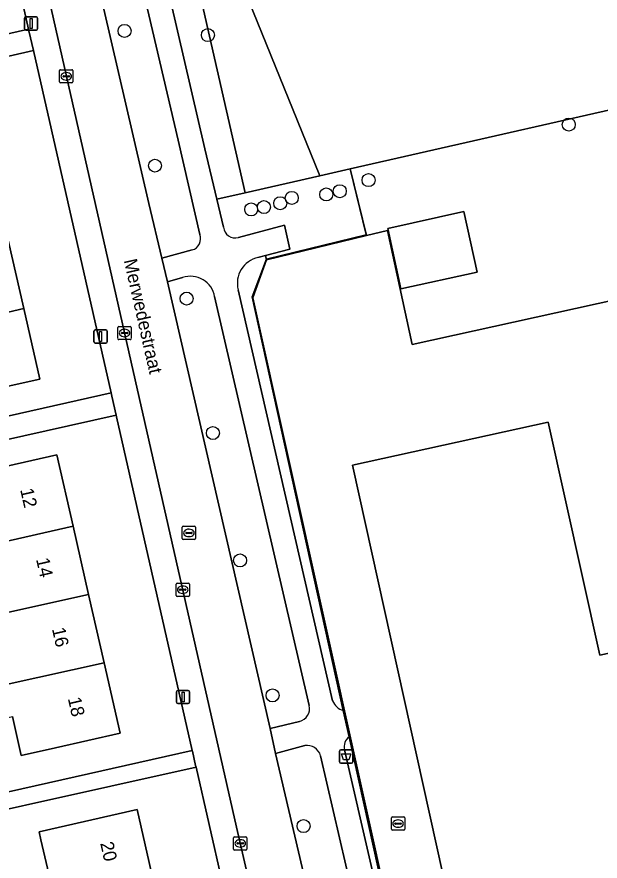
# Model space of a CAD drawing. Extents: x 157320 to 158835, y 386650 to 388491.
# Drawn here: x 157767.5 to 157811.4, y 387636.3 to 387699.9 of the extents above; entities that cross this region are included whole.
import ezdxf

# ---------------------------------------------------------------- set-up
doc = ezdxf.new("R2010")
doc.units = 0
for name, color, linetype in [('IMGEO_Afvalbak', 7, 'Continuous'), ('IMGEO_Boom', 7, 'Continuous'), ('IMGEO_Erf', 7, 'Continuous'), ('IMGEO_Groenvoorziening', 7, 'Continuous'), ('IMGEO_Hek', 7, 'Continuous'), ('IMGEO_Kolk', 7, 'Continuous'), ('IMGEO_Lichtmast', 7, 'Continuous'), ('IMGEO_Openbare_ruimte_label', 7, 'Continuous'), ('IMGEO_Pand', 7, 'Continuous'), ('IMGEO_Pand_nummerreeks', 7, 'Continuous'), ('IMGEO_Parkeervlak_open', 7, 'Continuous'), ('IMGEO_Rijbaan_lokaal_open', 7, 'Continuous'), ('IMGEO_Rioolput', 7, 'Continuous'), ('IMGEO_Voetpad_halfverhard', 7, 'Continuous'), ('IMGEO_Voetpad_open', 7, 'Continuous')]:
    doc.layers.add(name, color=color, linetype=linetype)

msp = doc.modelspace()

# ---------------------------------------------------------------- linework, layer by layer
at = {"layer": 'IMGEO_Afvalbak'}
for p, q in [((157791.814, 387643.776), (157791.814, 387644.576)), ((157791.814, 387644.576), (157791.814, 387643.776)), ((157791.914, 387644.676), (157792.704, 387644.676)), ((157792.704, 387644.676), (157791.914, 387644.676)), ((157792.804, 387644.576), (157792.804, 387643.776)), ((157792.804, 387643.776), (157792.804, 387644.576)), ((157792.704, 387643.676), (157791.914, 387643.676)), ((157791.914, 387643.676), (157792.704, 387643.676))]:
    msp.add_line(p, q, dxfattribs=at)
msp.add_lwpolyline([(157791.957, 387644.39), (157792.661, 387644.39), (157792.512, 387643.92), (157792.106, 387643.92), (157791.957, 387644.39)], dxfattribs=at)
for centre, start, end in [((157791.914, 387644.576), 90, 180), ((157791.914, 387644.576), 90, 180), ((157792.704, 387644.576), 0, 90), ((157792.704, 387644.576), 360, 90), ((157791.914, 387643.776), 180, 270), ((157791.914, 387643.776), 180, 270), ((157792.704, 387643.776), 270, 0), ((157792.704, 387643.776), 270, 0)]:
    msp.add_arc(centre, 0.1, start, end, dxfattribs=at)
at = {"layer": 'IMGEO_Boom'}
for centre in [(157775.609, 387698.881), (157781.893, 387698.565), (157809.078, 387691.821), (157777.905, 387688.72), (157793.996, 387687.63), (157790.81, 387686.549), (157791.828, 387686.798), (157787.337, 387685.891), (157788.21, 387686.292), (157785.151, 387685.42), (157786.115, 387685.598), (157780.29, 387678.698), (157782.268, 387668.563), (157784.312, 387658.961), (157786.76, 387648.787), (157789.095, 387638.93)]:
    msp.add_circle(centre, 0.489, dxfattribs=at)
at = {"layer": 'IMGEO_Erf'}
for points in [[(157744.821, 387693.675), (157768.381, 387699.017), (157764.859, 387714.548)], [(157784.941, 387701.215), (157790.321, 387687.956), (157792.617, 387688.478), (157819.163, 387694.512)], [(157748.731, 387665.763), (157774.601, 387671.588), (157768.748, 387697.397), (157745.976, 387692.171)], [(157766.849, 387683.112), (157768.019, 387677.941), (157769.219, 387672.637), (157764.343, 387671.533)], [(157756.011, 387639.067), (157780.714, 387644.628), (157775.009, 387669.789), (157774.984, 387669.899), (157748.592, 387664.011)], [(157763.513, 387665.337), (157770.505, 387666.932), (157771.734, 387661.545), (157772.908, 387656.394), (157774.083, 387651.242), (157775.292, 387645.942), (157770.418, 387644.831), (157767.833, 387644.241), (157767.158, 387647.199)], [(157786.883, 387617.427), (157781, 387643.367), (157755.052, 387637.604), (157750.85, 387636.671), (157750.482, 387636.589), (157751.038, 387633.845)], [(157769.895, 387635.327), (157769.305, 387637.903), (157769.173, 387638.5), (157776.551, 387640.189), (157777.77, 387634.865)]]:
    msp.add_lwpolyline(points, dxfattribs=at)
at = {"layer": 'IMGEO_Groenvoorziening'}
for points in [[(157781.285, 387683.528), (157779.645, 387690.655), (157777.159, 387701.293), (157772.834, 387719.515), (157770.315, 387730.462), (157767.54, 387729.135), (157767.721, 387727.843), (157768.836, 387723.063), (157770.575, 387715.53), (157777.429, 387685.881), (157778.41, 387681.752), (157780.707, 387682.368)], [(157819.163, 387694.512), (157792.617, 387688.478), (157793.85, 387683.459), (157795.419, 387683.841), (157797.286, 387675.235), (157829.765, 387682.405)], [(157792.617, 387688.478), (157790.321, 387687.956), (157784.703, 387686.679), (157782.572, 387686.195), (157783.074, 387684.079)], [(157784.185, 387683.301), (157787.667, 387684.235), (157788.066, 387682.433), (157786.231, 387681.945), (157786.315, 387681.625), (157793.85, 387683.459), (157792.617, 387688.478)], [(157786.315, 387681.625), (157786.231, 387681.945), (157785.66, 387681.793)], [(157792.188, 387644.685), (157802.528, 387599.779), (157802.788, 387599.832), (157801.253, 387606.747), (157785.269, 387678.768), (157786.315, 387681.625)], [(157779.986, 387680.279), (157778.84, 387679.961), (157786.577, 387646.289), (157788.786, 387646.819)], [(157784.175, 387679.368), (157791.291, 387648.372)], [(157789.521, 387648.019), (157782.399, 387678.849)], [(157792.087, 387647.658), (157792.525, 387645.671)], [(157789.187, 387645.002), (157786.982, 387644.405), (157789.443, 387633.877), (157797.77, 387598.149), (157800.871, 387598.887), (157790.384, 387644.236)]]:
    msp.add_lwpolyline(points, dxfattribs=at)
msp.add_lwpolyline([(157801.175, 387685.256), (157802.17, 387680.689), (157796.438, 387679.428), (157795.445, 387683.997)], close=True, dxfattribs=at)
for centre, radius, start, end in [((157783.962, 387684.164), 0.892, 185.49428, 284.50091), ((157780.464, 387683.213), 0.879, 286.05214, 20.97592), ((157786.076, 387679.871), 1.966, 102.21251, 194.82329), ((157780.588, 387678.544), 1.837, 9.5637, 109.13236), ((157792.362, 387648.766), 1.141, 200.17079, 256.04596), ((157788.553, 387647.787), 0.995, 283.53209, 13.49297), ((157793.147, 387644.908), 0.985, 129.18724, 193.07344), ((157789.358, 387643.951), 1.065, 15.51084, 99.25611)]:
    msp.add_arc(centre, radius, start, end, dxfattribs=at)
at = {"layer": 'IMGEO_Hek'}
for points in [[(157784.941, 387701.215), (157790.321, 387687.956)], [(157793.824, 387683.52), (157792.617, 387688.478)], [(157792.087, 387647.658), (157785.216, 387678.831), (157786.296, 387681.687), (157793.824, 387683.52)], [(157802.675, 387599.617), (157792.525, 387645.671)]]:
    msp.add_lwpolyline(points, dxfattribs=at)
at = {"layer": 'IMGEO_Kolk'}
for p, q in [((157770.721, 387695.032), (157770.721, 387695.884)), ((157770.796, 387695.958), (157771.648, 387695.958)), ((157771.722, 387695.884), (157771.722, 387695.032)), ((157770.98, 387695.452), (157770.98, 387695.464)), ((157771.418, 387695.415), (157771.02, 387695.415)), ((157771.023, 387695.501), (157771.421, 387695.501)), ((157771.209, 387695.738), (157771.234, 387695.738)), ((157771.464, 387695.464), (157771.464, 387695.452)), ((157771.648, 387694.958), (157770.796, 387694.958)), ((157771.232, 387695.178), (157771.207, 387695.178)), ((157775.112, 387675.679), (157775.112, 387676.531)), ((157775.187, 387676.605), (157776.039, 387676.605)), ((157775.6, 387676.385), (157775.625, 387676.385)), ((157776.113, 387676.531), (157776.113, 387675.679)), ((157776.039, 387675.605), (157775.187, 387675.605)), ((157775.371, 387676.099), (157775.371, 387676.111)), ((157775.809, 387676.062), (157775.411, 387676.062)), ((157775.414, 387676.148), (157775.812, 387676.148)), ((157775.623, 387675.825), (157775.598, 387675.825)), ((157775.855, 387676.111), (157775.855, 387676.099)), ((157779.496, 387656.325), (157779.496, 387657.177)), ((157779.571, 387657.251), (157780.423, 387657.251)), ((157780.497, 387657.177), (157780.497, 387656.325)), ((157779.755, 387656.745), (157779.755, 387656.757)), ((157780.193, 387656.708), (157779.795, 387656.708)), ((157779.798, 387656.794), (157780.196, 387656.794)), ((157780.007, 387656.471), (157779.982, 387656.471)), ((157779.984, 387657.031), (157780.009, 387657.031)), ((157780.239, 387656.757), (157780.239, 387656.745)), ((157780.423, 387656.251), (157779.571, 387656.251)), ((157783.832, 387637.2), (157783.832, 387638.052)), ((157783.907, 387638.126), (157784.759, 387638.126)), ((157784.833, 387638.052), (157784.833, 387637.2)), ((157784.091, 387637.62), (157784.091, 387637.632)), ((157784.529, 387637.583), (157784.131, 387637.583)), ((157784.134, 387637.669), (157784.532, 387637.669)), ((157784.343, 387637.346), (157784.318, 387637.346)), ((157784.32, 387637.906), (157784.345, 387637.906)), ((157784.575, 387637.632), (157784.575, 387637.62)), ((157784.759, 387637.126), (157783.907, 387637.126))]:
    msp.add_line(p, q, dxfattribs=at)
for points in [[(157770.721, 387695.032), (157770.721, 387695.884)], [(157770.796, 387695.958), (157771.648, 387695.958)], [(157771.722, 387695.884), (157771.722, 387695.032)], [(157771.648, 387694.958), (157770.796, 387694.958)], [(157775.112, 387675.679), (157775.112, 387676.531)], [(157775.187, 387676.605), (157776.039, 387676.605)], [(157776.113, 387676.531), (157776.113, 387675.679)], [(157776.039, 387675.605), (157775.187, 387675.605)], [(157779.496, 387656.325), (157779.496, 387657.177)], [(157779.571, 387657.251), (157780.423, 387657.251)], [(157780.497, 387657.177), (157780.497, 387656.325)], [(157780.423, 387656.251), (157779.571, 387656.251)], [(157783.832, 387637.2), (157783.832, 387638.052)], [(157783.907, 387638.126), (157784.759, 387638.126)], [(157784.833, 387638.052), (157784.833, 387637.2)], [(157784.759, 387637.126), (157783.907, 387637.126)]]:
    msp.add_lwpolyline(points, dxfattribs=at)
for centre, radius, start, end in [((157770.798, 387695.882), 0.0765, 91.55205, 178.44795), ((157770.798, 387695.882), 0.0765, 91.55205, 178.44795), ((157771.646, 387695.882), 0.0765, 1.55205, 88.44795), ((157771.646, 387695.882), 0.0765, 1.55205, 88.44795), ((157771.02, 387695.461), 0.0403, 85.87752, 175.75265), ((157771.017, 387695.451), 0.0366, 178.93798, 274.71019), ((157771.421, 387695.458), 0.043, 264.86636, 352.45326), ((157771.425, 387695.463), 0.0386, 1.73085, 96.63898), ((157770.798, 387695.034), 0.0765, 181.55205, 268.44795), ((157770.798, 387695.034), 0.0765, 181.55205, 268.44795), ((157771.646, 387695.034), 0.0765, 271.55205, 358.44795), ((157771.646, 387695.034), 0.0765, 271.55205, 358.44795), ((157775.189, 387676.529), 0.0765, 91.55205, 178.44795), ((157775.189, 387676.529), 0.0765, 91.55205, 178.44795), ((157776.037, 387676.529), 0.0765, 1.55205, 88.44795), ((157776.037, 387676.529), 0.0765, 1.55205, 88.44795), ((157775.189, 387675.681), 0.0765, 181.55205, 268.44795), ((157775.189, 387675.681), 0.0765, 181.55205, 268.44795), ((157775.411, 387676.108), 0.0403, 85.87752, 175.75265), ((157775.408, 387676.098), 0.0366, 178.93798, 274.71019), ((157775.812, 387676.105), 0.043, 264.86636, 352.45326), ((157775.816, 387676.11), 0.0386, 1.73085, 96.63898), ((157776.037, 387675.681), 0.0765, 271.55205, 358.44795), ((157776.037, 387675.681), 0.0765, 271.55205, 358.44795), ((157779.573, 387657.175), 0.0765, 91.55205, 178.44795), ((157779.573, 387657.175), 0.0765, 91.55205, 178.44795), ((157780.421, 387657.175), 0.0765, 1.55205, 88.44795), ((157780.421, 387657.175), 0.0765, 1.55205, 88.44795), ((157779.795, 387656.754), 0.0403, 85.87752, 175.75265), ((157779.792, 387656.744), 0.0366, 178.93798, 274.71019), ((157780.196, 387656.751), 0.043, 264.86636, 352.45326), ((157780.2, 387656.756), 0.0386, 1.73085, 96.63898), ((157779.573, 387656.327), 0.0765, 181.55205, 268.44795), ((157779.573, 387656.327), 0.0765, 181.55205, 268.44795), ((157780.421, 387656.327), 0.0765, 271.55205, 358.44795), ((157780.421, 387656.327), 0.0765, 271.55205, 358.44795), ((157783.909, 387638.05), 0.0765, 91.55205, 178.44795), ((157783.909, 387638.05), 0.0765, 91.55205, 178.44795), ((157784.757, 387638.05), 0.0765, 1.55205, 88.44795), ((157784.757, 387638.05), 0.0765, 1.55205, 88.44795), ((157784.131, 387637.629), 0.0403, 85.87752, 175.75265), ((157784.128, 387637.619), 0.0366, 178.93798, 274.71019), ((157784.532, 387637.626), 0.043, 264.86636, 352.45326), ((157784.536, 387637.631), 0.0386, 1.73085, 96.63898), ((157783.909, 387637.202), 0.0765, 181.55205, 268.44795), ((157783.909, 387637.202), 0.0765, 181.55205, 268.44795), ((157784.757, 387637.202), 0.0765, 271.55205, 358.44795), ((157784.757, 387637.202), 0.0765, 271.55205, 358.44795)]:
    msp.add_arc(centre, radius, start, end, dxfattribs=at)
for centre, major_axis, ratio, start_param, end_param in [((157771.208, 387695.458), (-0.387, 0.002), 0.722429, 4.712389, 7.853982), ((157771.233, 387695.458), (-0.39, 0.002), 0.717154, 1.570796, 4.712389), ((157775.599, 387676.105), (-0.387, 0.002), 0.722429, 4.712389, 7.853982), ((157775.624, 387676.105), (-0.39, 0.002), 0.717154, 1.570796, 4.712389), ((157779.983, 387656.751), (-0.387, 0.002), 0.722429, 4.712389, 7.853982), ((157780.008, 387656.751), (-0.39, 0.002), 0.717154, 1.570796, 4.712389), ((157784.319, 387637.626), (-0.387, 0.002), 0.722429, 4.712389, 7.853982), ((157784.344, 387637.626), (-0.39, 0.002), 0.717154, 1.570796, 4.712389)]:
    msp.add_ellipse(centre, major_axis=major_axis, ratio=ratio, start_param=start_param, end_param=end_param, dxfattribs=at)
at = {"layer": 'IMGEO_Lichtmast'}
for p, q in [((157768.076, 387699.039), (157768.076, 387699.839)), ((157768.076, 387699.839), (157768.076, 387699.039)), ((157768.176, 387699.939), (157768.966, 387699.939)), ((157768.966, 387699.939), (157768.176, 387699.939)), ((157769.066, 387699.839), (157769.066, 387699.039)), ((157769.066, 387699.039), (157769.066, 387699.839)), ((157768.966, 387698.939), (157768.176, 387698.939)), ((157768.176, 387698.939), (157768.966, 387698.939)), ((157773.308, 387675.447), (157773.308, 387676.247)), ((157773.308, 387676.247), (157773.308, 387675.447)), ((157773.408, 387676.347), (157774.198, 387676.347)), ((157774.198, 387676.347), (157773.408, 387676.347)), ((157774.298, 387676.247), (157774.298, 387675.447)), ((157774.298, 387675.447), (157774.298, 387676.247)), ((157774.198, 387675.347), (157773.408, 387675.347)), ((157773.408, 387675.347), (157774.198, 387675.347)), ((157779.521, 387648.263), (157779.521, 387649.063)), ((157779.521, 387649.063), (157779.521, 387648.263)), ((157779.621, 387649.163), (157780.411, 387649.163)), ((157780.411, 387649.163), (157779.621, 387649.163)), ((157780.511, 387649.063), (157780.511, 387648.263)), ((157780.511, 387648.263), (157780.511, 387649.063)), ((157780.411, 387648.163), (157779.621, 387648.163)), ((157779.621, 387648.163), (157780.411, 387648.163))]:
    msp.add_line(p, q, dxfattribs=at)
for points in [[(157768.496, 387699.814), (157768.646, 387699.814), (157768.646, 387699.064), (157768.496, 387699.064), (157768.496, 387699.814)], [(157773.728, 387676.222), (157773.878, 387676.222), (157773.878, 387675.472), (157773.728, 387675.472), (157773.728, 387676.222)], [(157779.941, 387649.038), (157780.091, 387649.038), (157780.091, 387648.288), (157779.941, 387648.288), (157779.941, 387649.038)]]:
    msp.add_lwpolyline(points, dxfattribs=at)
for centre, start, end in [((157768.176, 387699.839), 90, 180), ((157768.176, 387699.839), 90, 180), ((157768.966, 387699.839), 0, 90), ((157768.966, 387699.839), 360, 90), ((157768.176, 387699.039), 180, 270), ((157768.176, 387699.039), 180, 270), ((157768.966, 387699.039), 270, 0), ((157768.966, 387699.039), 270, 0), ((157773.408, 387676.247), 90, 180), ((157773.408, 387676.247), 90, 180), ((157774.198, 387676.247), 0, 90), ((157774.198, 387676.247), 360, 90), ((157773.408, 387675.447), 180, 270), ((157773.408, 387675.447), 180, 270), ((157774.198, 387675.447), 270, 0), ((157774.198, 387675.447), 270, 0), ((157779.621, 387649.063), 90, 180), ((157779.621, 387649.063), 90, 180), ((157780.411, 387649.063), 0, 90), ((157780.411, 387649.063), 360, 90), ((157779.621, 387648.263), 180, 270), ((157779.621, 387648.263), 180, 270), ((157780.411, 387648.263), 270, 0), ((157780.411, 387648.263), 270, 0)]:
    msp.add_arc(centre, 0.1, start, end, dxfattribs=at)
at = {"layer": 'IMGEO_Pand'}
for points in [[(157801.175, 387685.256), (157795.445, 387683.997), (157796.438, 387679.428), (157802.17, 387680.689)], [(157766.849, 387683.112), (157759.372, 387681.419), (157760.079, 387678.295), (157751.782, 387676.418), (157750.18, 387676.056), (157750.672, 387673.883), (157768.019, 387677.941)], [(157768.019, 387677.941), (157750.672, 387673.883), (157751.198, 387671.555), (157752.8, 387671.917), (157761.098, 387673.795), (157761.743, 387670.945), (157764.343, 387671.533), (157769.219, 387672.637)], [(157834.01, 387656.824), (157836.938, 387657.47), (157833.032, 387675.058), (157831.465, 387674.711), (157818.262, 387671.784), (157822.16, 387654.192), (157811.41, 387651.812), (157807.526, 387669.385), (157792.784, 387666.135), (157804.441, 387613.378), (157819.201, 387616.636), (157815.303, 387634.218), (157826.064, 387636.591), (157829.979, 387618.997), (157844.662, 387622.26), (157844.755, 387622.28), (157840.846, 387639.889), (157837.916, 387639.217)], [(157754.167, 387657.555), (157771.734, 387661.545), (157770.505, 387666.932), (157763.513, 387665.337), (157763.126, 387665.249), (157763.861, 387662.026), (157755.582, 387660.138), (157753.68, 387659.708)], [(157765.524, 387654.759), (157772.908, 387656.394), (157771.734, 387661.545), (157754.167, 387657.555), (157754.697, 387655.213), (157756.607, 387655.645), (157764.891, 387657.534)], [(157756.665, 387647.383), (157774.083, 387651.242), (157772.908, 387656.394), (157765.524, 387654.759), (157766.213, 387651.735), (157757.862, 387649.831), (157756.196, 387649.454)], [(157767.158, 387647.199), (157767.833, 387644.241), (157770.418, 387644.831), (157775.292, 387645.942), (157774.083, 387651.242), (157756.665, 387647.383), (157756.691, 387647.268), (157757.218, 387644.935), (157758.892, 387645.314)], [(157760.394, 387630.958), (157777.77, 387634.865), (157776.551, 387640.189), (157769.173, 387638.5), (157769.305, 387637.903), (157769.895, 387635.327), (157761.603, 387633.429), (157759.916, 387633.043)]]:
    msp.add_lwpolyline(points, close=True, dxfattribs=at)
at = {"layer": 'IMGEO_Parkeervlak_open'}
msp.add_lwpolyline([(157791.244, 387607.599), (157784.055, 387638.839), (157776.417, 387672.566), (157766.969, 387714.367), (157765.578, 387720.19), (157765.157, 387720.104), (157765.927, 387717.011), (157764.14, 387717.866), (157764.859, 387714.548), (157768.381, 387699.017), (157768.41, 387698.888), (157768.748, 387697.397), (157774.601, 387671.588), (157774.654, 387671.352), (157774.984, 387669.899), (157775.009, 387669.789), (157780.714, 387644.628), (157780.723, 387644.589), (157780.969, 387643.505), (157781, 387643.367), (157786.883, 387617.427)], dxfattribs=at)
for points in [[(157784.941, 387701.215), (157781.937, 387708.618), (157779.896, 387707.789), (157784.703, 387686.679), (157790.321, 387687.956)], [(157777.749, 387706.918), (157778.574, 387703.365), (157781.672, 387689.989), (157782.572, 387686.195), (157784.703, 387686.679), (157779.896, 387707.789)]]:
    msp.add_lwpolyline(points, close=True, dxfattribs=at)
at = {"layer": 'IMGEO_Rijbaan_lokaal_open'}
msp.add_lwpolyline([(157789.443, 387633.877), (157786.982, 387644.405), (157786.577, 387646.289), (157778.84, 387679.961), (157778.41, 387681.752), (157777.429, 387685.881), (157770.575, 387715.53), (157768.836, 387723.063), (157765.102, 387722.238), (157765.578, 387720.19), (157766.969, 387714.367), (157776.417, 387672.566), (157784.055, 387638.839), (157791.244, 387607.599), (157794.251, 387594.621), (157794.686, 387592.742)], dxfattribs=at)
at = {"layer": 'IMGEO_Rioolput'}
for p, q in [((157780.039, 387661.534), (157780.891, 387661.534)), ((157779.964, 387660.608), (157779.964, 387661.46)), ((157780.223, 387661.028), (157780.223, 387661.04)), ((157780.661, 387660.991), (157780.263, 387660.991)), ((157780.266, 387661.077), (157780.664, 387661.077)), ((157780.452, 387661.314), (157780.477, 387661.314)), ((157780.707, 387661.04), (157780.707, 387661.028)), ((157780.965, 387661.46), (157780.965, 387660.608)), ((157780.891, 387660.534), (157780.039, 387660.534)), ((157780.475, 387660.754), (157780.45, 387660.754)), ((157795.722, 387638.694), (157795.722, 387639.546)), ((157795.797, 387639.62), (157796.649, 387639.62)), ((157796.21, 387639.4), (157796.235, 387639.4)), ((157796.723, 387639.546), (157796.723, 387638.694)), ((157796.649, 387638.62), (157795.797, 387638.62)), ((157795.981, 387639.114), (157795.981, 387639.126)), ((157796.419, 387639.077), (157796.021, 387639.077)), ((157796.024, 387639.163), (157796.422, 387639.163)), ((157796.233, 387638.84), (157796.208, 387638.84)), ((157796.465, 387639.126), (157796.465, 387639.114))]:
    msp.add_line(p, q, dxfattribs=at)
for points in [[(157780.039, 387661.534), (157780.891, 387661.534)], [(157779.964, 387660.608), (157779.964, 387661.46)], [(157780.965, 387661.46), (157780.965, 387660.608)], [(157780.891, 387660.534), (157780.039, 387660.534)], [(157795.722, 387638.694), (157795.722, 387639.546)], [(157795.797, 387639.62), (157796.649, 387639.62)], [(157796.723, 387639.546), (157796.723, 387638.694)], [(157796.649, 387638.62), (157795.797, 387638.62)]]:
    msp.add_lwpolyline(points, dxfattribs=at)
for centre, radius, start, end in [((157780.041, 387661.458), 0.0765, 91.55205, 178.44795), ((157780.041, 387661.458), 0.0765, 91.55205, 178.44795), ((157780.889, 387661.458), 0.0765, 1.55205, 88.44795), ((157780.889, 387661.458), 0.0765, 1.55205, 88.44795), ((157780.263, 387661.037), 0.0403, 85.87752, 175.75265), ((157780.26, 387661.027), 0.0366, 178.93798, 274.71019), ((157780.664, 387661.034), 0.043, 264.86636, 352.45326), ((157780.668, 387661.039), 0.0386, 1.73085, 96.63898), ((157780.041, 387660.61), 0.0765, 181.55205, 268.44795), ((157780.041, 387660.61), 0.0765, 181.55205, 268.44795), ((157780.889, 387660.61), 0.0765, 271.55205, 358.44795), ((157780.889, 387660.61), 0.0765, 271.55205, 358.44795), ((157795.799, 387639.544), 0.0765, 91.55205, 178.44795), ((157795.799, 387639.544), 0.0765, 91.55205, 178.44795), ((157796.647, 387639.544), 0.0765, 1.55205, 88.44795), ((157796.647, 387639.544), 0.0765, 1.55205, 88.44795), ((157795.799, 387638.696), 0.0765, 181.55205, 268.44795), ((157795.799, 387638.696), 0.0765, 181.55205, 268.44795), ((157796.021, 387639.123), 0.0403, 85.87752, 175.75265), ((157796.018, 387639.113), 0.0366, 178.93798, 274.71019), ((157796.422, 387639.12), 0.043, 264.86636, 352.45326), ((157796.426, 387639.125), 0.0386, 1.73085, 96.63898), ((157796.647, 387638.696), 0.0765, 271.55205, 358.44795), ((157796.647, 387638.696), 0.0765, 271.55205, 358.44795)]:
    msp.add_arc(centre, radius, start, end, dxfattribs=at)
for centre, major_axis, ratio, start_param, end_param in [((157780.451, 387661.034), (-0.387, 0.002), 0.722429, 4.712389, 7.853982), ((157780.476, 387661.034), (-0.39, 0.002), 0.717154, 1.570796, 4.712389), ((157796.209, 387639.12), (-0.387, 0.002), 0.722429, 4.712389, 7.853982), ((157796.234, 387639.12), (-0.39, 0.002), 0.717154, 1.570796, 4.712389)]:
    msp.add_ellipse(centre, major_axis=major_axis, ratio=ratio, start_param=start_param, end_param=end_param, dxfattribs=at)
at = {"layer": 'IMGEO_Voetpad_halfverhard'}
for points in [[(157783.074, 387684.079), (157782.572, 387686.195), (157781.672, 387689.989), (157778.574, 387703.365), (157777.749, 387706.918), (157774.684, 387720.113), (157773.614, 387724.6), (157772.157, 387731.342), (157770.315, 387730.462), (157772.834, 387719.515), (157777.159, 387701.293), (157779.645, 387690.655), (157781.285, 387683.528)], [(157785.66, 387681.793), (157786.231, 387681.945), (157788.066, 387682.433), (157787.667, 387684.235), (157784.185, 387683.301)], [(157780.707, 387682.368), (157778.41, 387681.752), (157778.84, 387679.961), (157779.986, 387680.279)], [(157791.291, 387648.372), (157784.175, 387679.368)], [(157782.399, 387678.849), (157789.521, 387648.019)], [(157792.525, 387645.671), (157792.087, 387647.658)], [(157788.786, 387646.819), (157786.577, 387646.289), (157786.982, 387644.405), (157789.187, 387645.002)], [(157802.721, 387598.939), (157802.528, 387599.779), (157792.188, 387644.685)], [(157790.384, 387644.236), (157800.871, 387598.887), (157801.024, 387598.927), (157801.679, 387596.36), (157803.002, 387595.497), (157807.241, 387596.288)]]:
    msp.add_lwpolyline(points, dxfattribs=at)
for centre, radius, start, end in [((157783.962, 387684.164), 0.892, 185.49428, 284.50091), ((157780.464, 387683.213), 0.879, 286.05214, 20.97592), ((157786.076, 387679.871), 1.966, 102.21251, 194.82329), ((157780.588, 387678.544), 1.837, 9.5637, 109.13236), ((157792.362, 387648.766), 1.141, 200.17079, 256.04596), ((157788.553, 387647.787), 0.995, 283.53209, 13.49297), ((157793.147, 387644.908), 0.985, 129.18724, 193.07344), ((157789.358, 387643.951), 1.065, 15.51084, 99.25611)]:
    msp.add_arc(centre, radius, start, end, dxfattribs=at)
at = {"layer": 'IMGEO_Voetpad_open'}
for points in [[(157768.748, 387697.397), (157768.41, 387698.888), (157768.381, 387699.017), (157744.821, 387693.675), (157741.294, 387683.711), (157739.786, 387680.465), (157741.426, 387679.633), (157741.759, 387680.551), (157742.647, 387682.998), (157743.618, 387685.675), (157745.976, 387692.171)], [(157774.984, 387669.899), (157774.654, 387671.352), (157774.601, 387671.588), (157748.731, 387665.763), (157744.827, 387664.884), (157745.18, 387663.207), (157748.592, 387664.011)], [(157781, 387643.367), (157780.969, 387643.505), (157780.723, 387644.589), (157780.714, 387644.628), (157756.011, 387639.067), (157750.589, 387637.847), (157750.85, 387636.671), (157755.052, 387637.604)]]:
    msp.add_lwpolyline(points, close=True, dxfattribs=at)
msp.add_lwpolyline([(157804.441, 387613.378), (157792.784, 387666.135), (157807.526, 387669.385), (157811.41, 387651.812), (157822.16, 387654.192), (157818.262, 387671.784), (157831.465, 387674.711), (157829.765, 387682.405), (157797.286, 387675.235), (157795.419, 387683.841), (157793.85, 387683.459), (157786.315, 387681.625), (157785.269, 387678.768), (157801.253, 387606.747)], dxfattribs=at)

# ---------------------------------------------------------------- texts
at = {"layer": 'IMGEO_Openbare_ruimte_label'}
msp.add_text('Merwedestraat', height=1, rotation=282.77124, dxfattribs=at).set_placement((157775.549, 387681.581))
at = {"layer": 'IMGEO_Pand_nummerreeks'}
for s, rotation, p in [('12', 282.8472, (157767.742, 387664.298)), ('14', 282.8472, (157768.939, 387659.048)), ('16', 282.8472, (157770.135, 387653.8)), ('18', 282.8455, (157771.333, 387648.551)), ('20', 282.89327, (157773.769, 387637.642))]:
    msp.add_text(s, height=1, rotation=rotation, dxfattribs=at).set_placement(p)

doc.saveas('drawing.dxf')
